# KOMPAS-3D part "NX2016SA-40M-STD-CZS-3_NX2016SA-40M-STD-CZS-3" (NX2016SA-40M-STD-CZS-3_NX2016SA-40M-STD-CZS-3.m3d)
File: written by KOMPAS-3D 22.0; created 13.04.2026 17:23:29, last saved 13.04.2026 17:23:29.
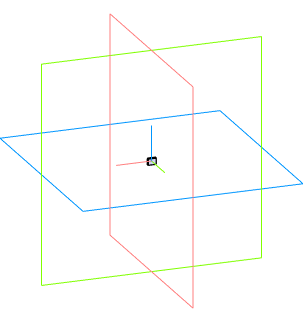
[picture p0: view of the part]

Document properties: Автор: Andrey; Полное имя файла: C:\Users\User1\Documents\NX2016SA-40M-STD-CZS-3_NX2016SA-40M-STD-CZS-3.m3d

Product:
- Part/product: NX2016SA-40M-STD-CZS-3_NX2016SA-40M-STD-CZS-3

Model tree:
1. Операция без истории:1
2. Операция без истории:2
3. Операция без истории:3
4. Операция без истории:4
5. Операция без истории:5
6. Операция без истории:6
